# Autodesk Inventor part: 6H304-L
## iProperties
Shininess: 0.0
Length Units: 11272
Angle Units: 11279
Time Units: 11290
Mass Units: 11286
Length Display Precision: 3
Angle Display Precision: 2
Created: 2002-07
Part Number: 6H304-L
Description: MARTIN HELICOID CONVEYOR SCREW
Document SubType Name: Modeling
Designer: CM
Density: 10.49
Volumn: 2.304646865681294
Area: 8.437628188859923
PropertySet Name: Model Information
Control State: 0
Master: False
Checked Out: False
Author: Cory McConnell
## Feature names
1. Extrusion2
2. Left
3. Right
4. Extrusion3
5. Extrusion4
